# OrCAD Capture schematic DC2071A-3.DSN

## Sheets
1 PAGE1: size Custom; rev: 1
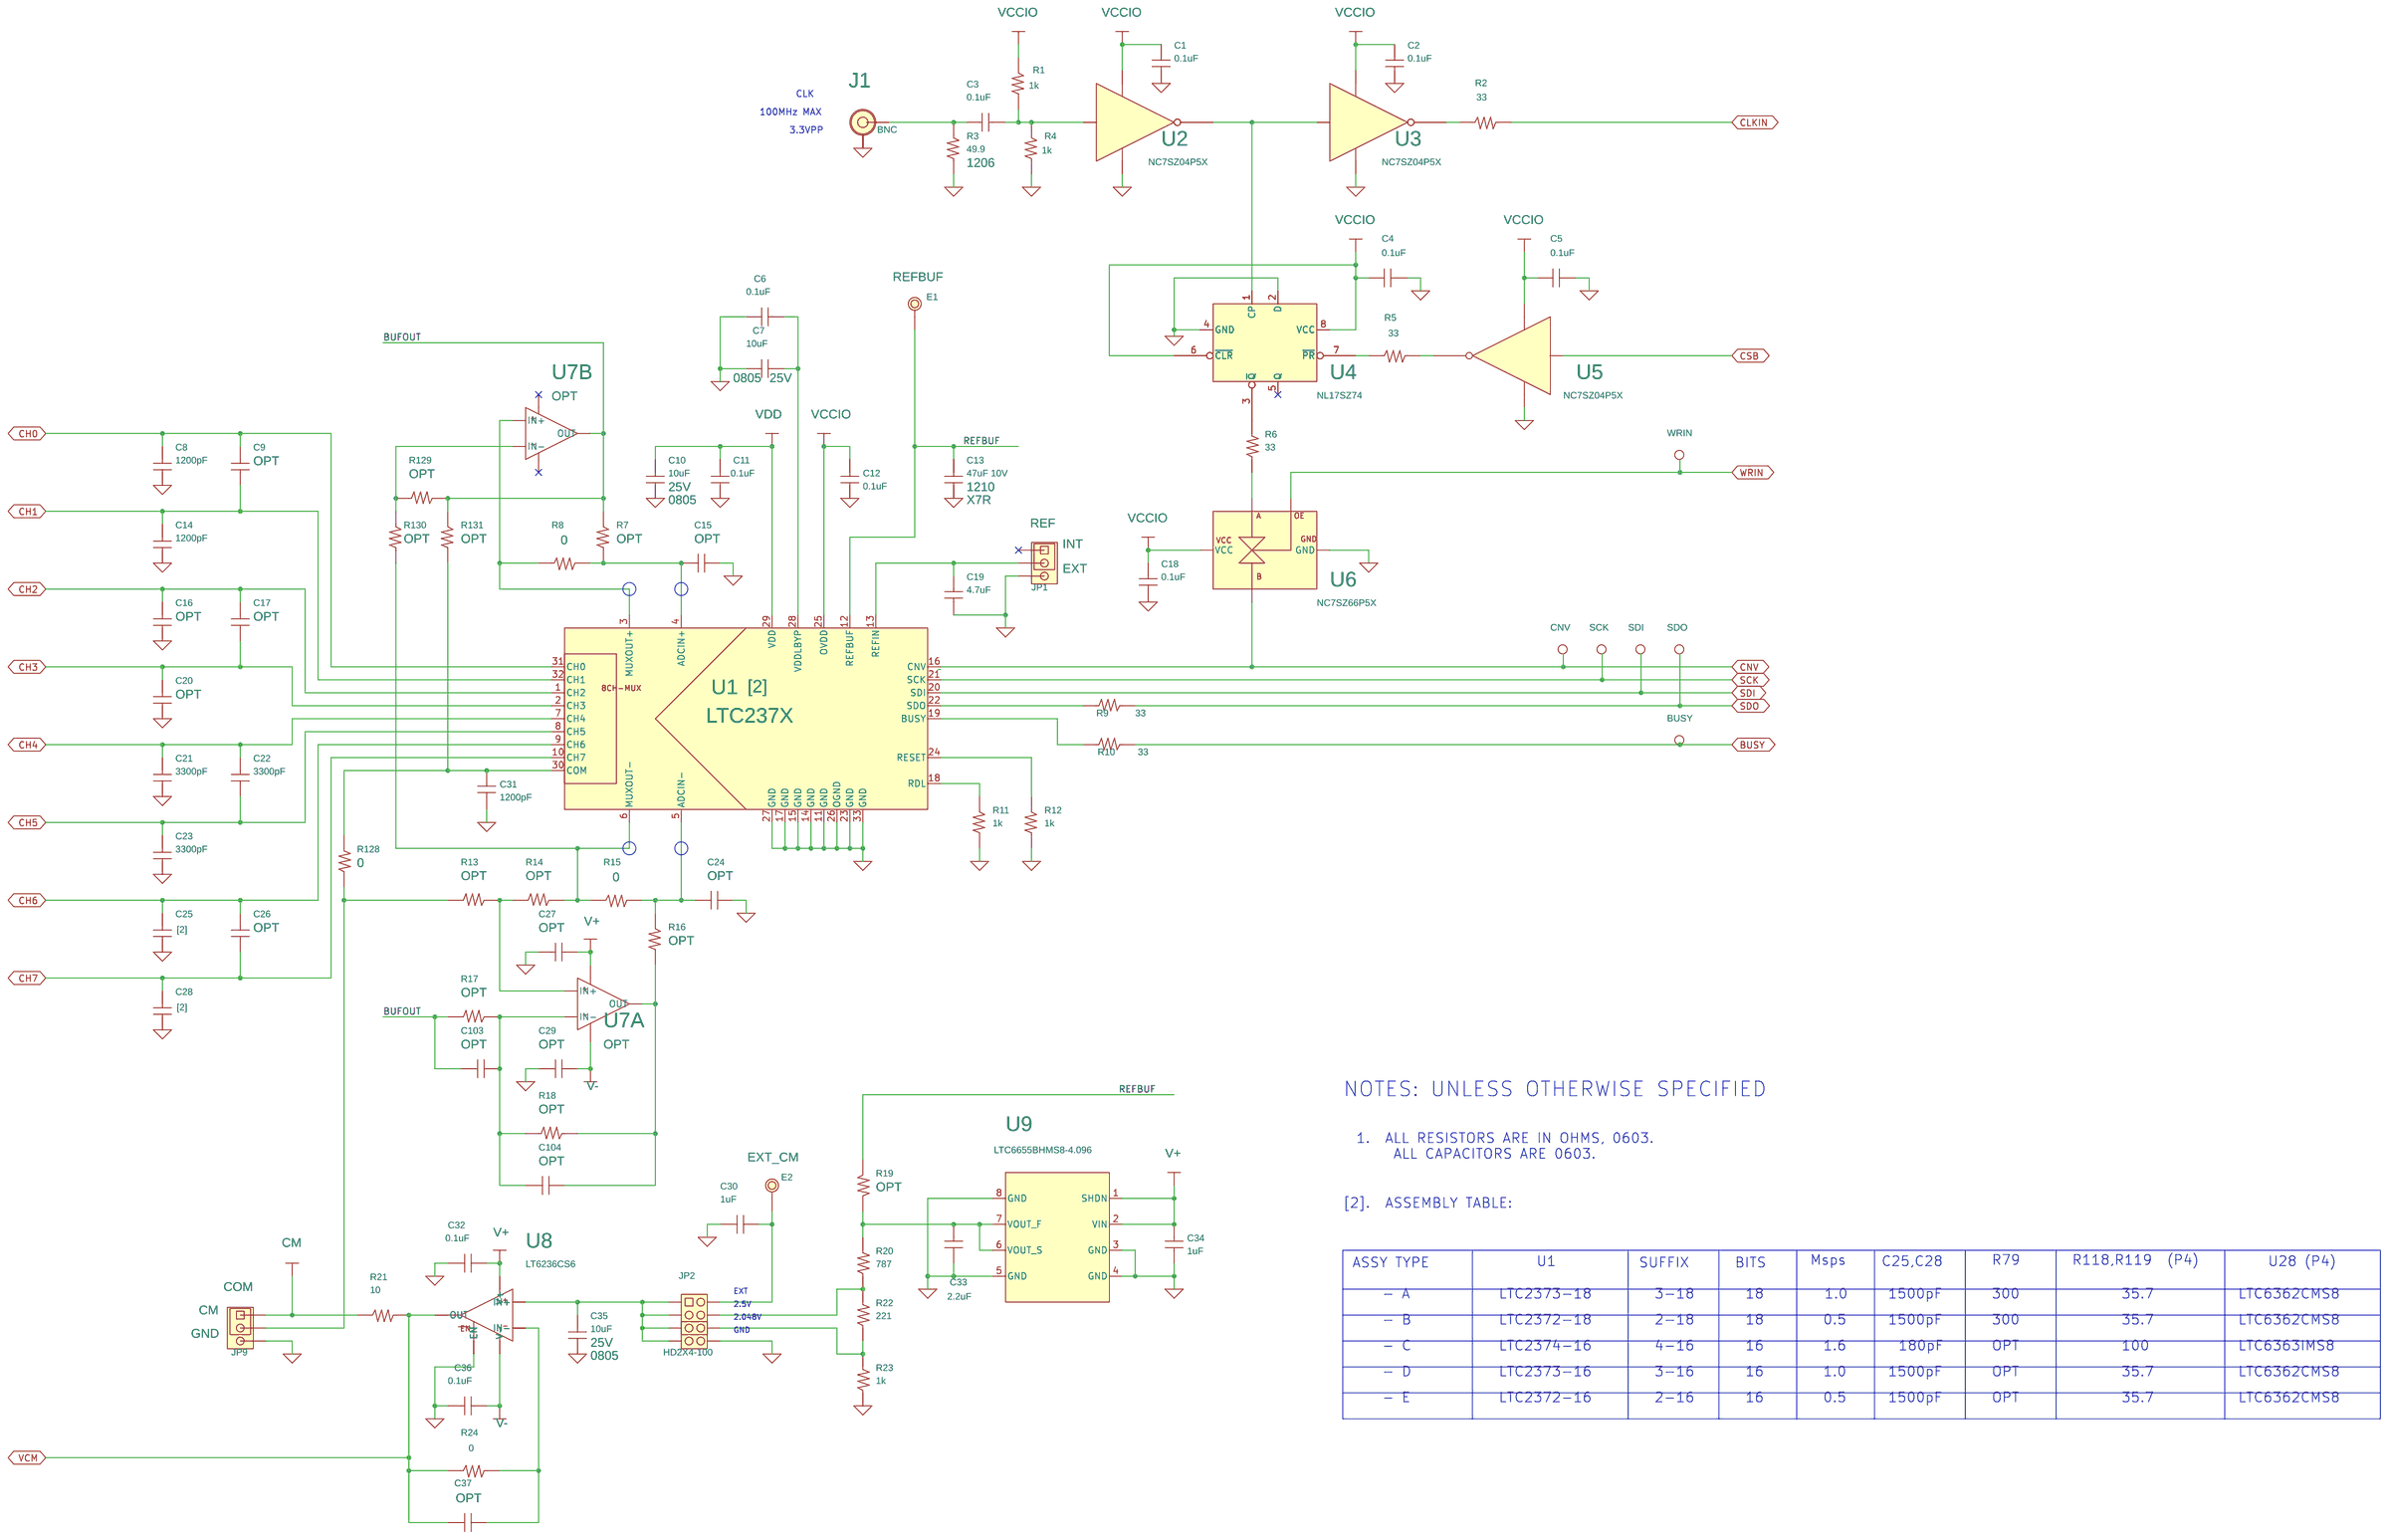
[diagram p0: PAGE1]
2 PAGE2: size B; title: 8-CHANNEL, HIGH SPEED, SERIAL, SAR, ADC; rev: 3; company: LTC237XCUH-18/16 FAMILY; note: DEMO CIRCUIT 2071A; note: B
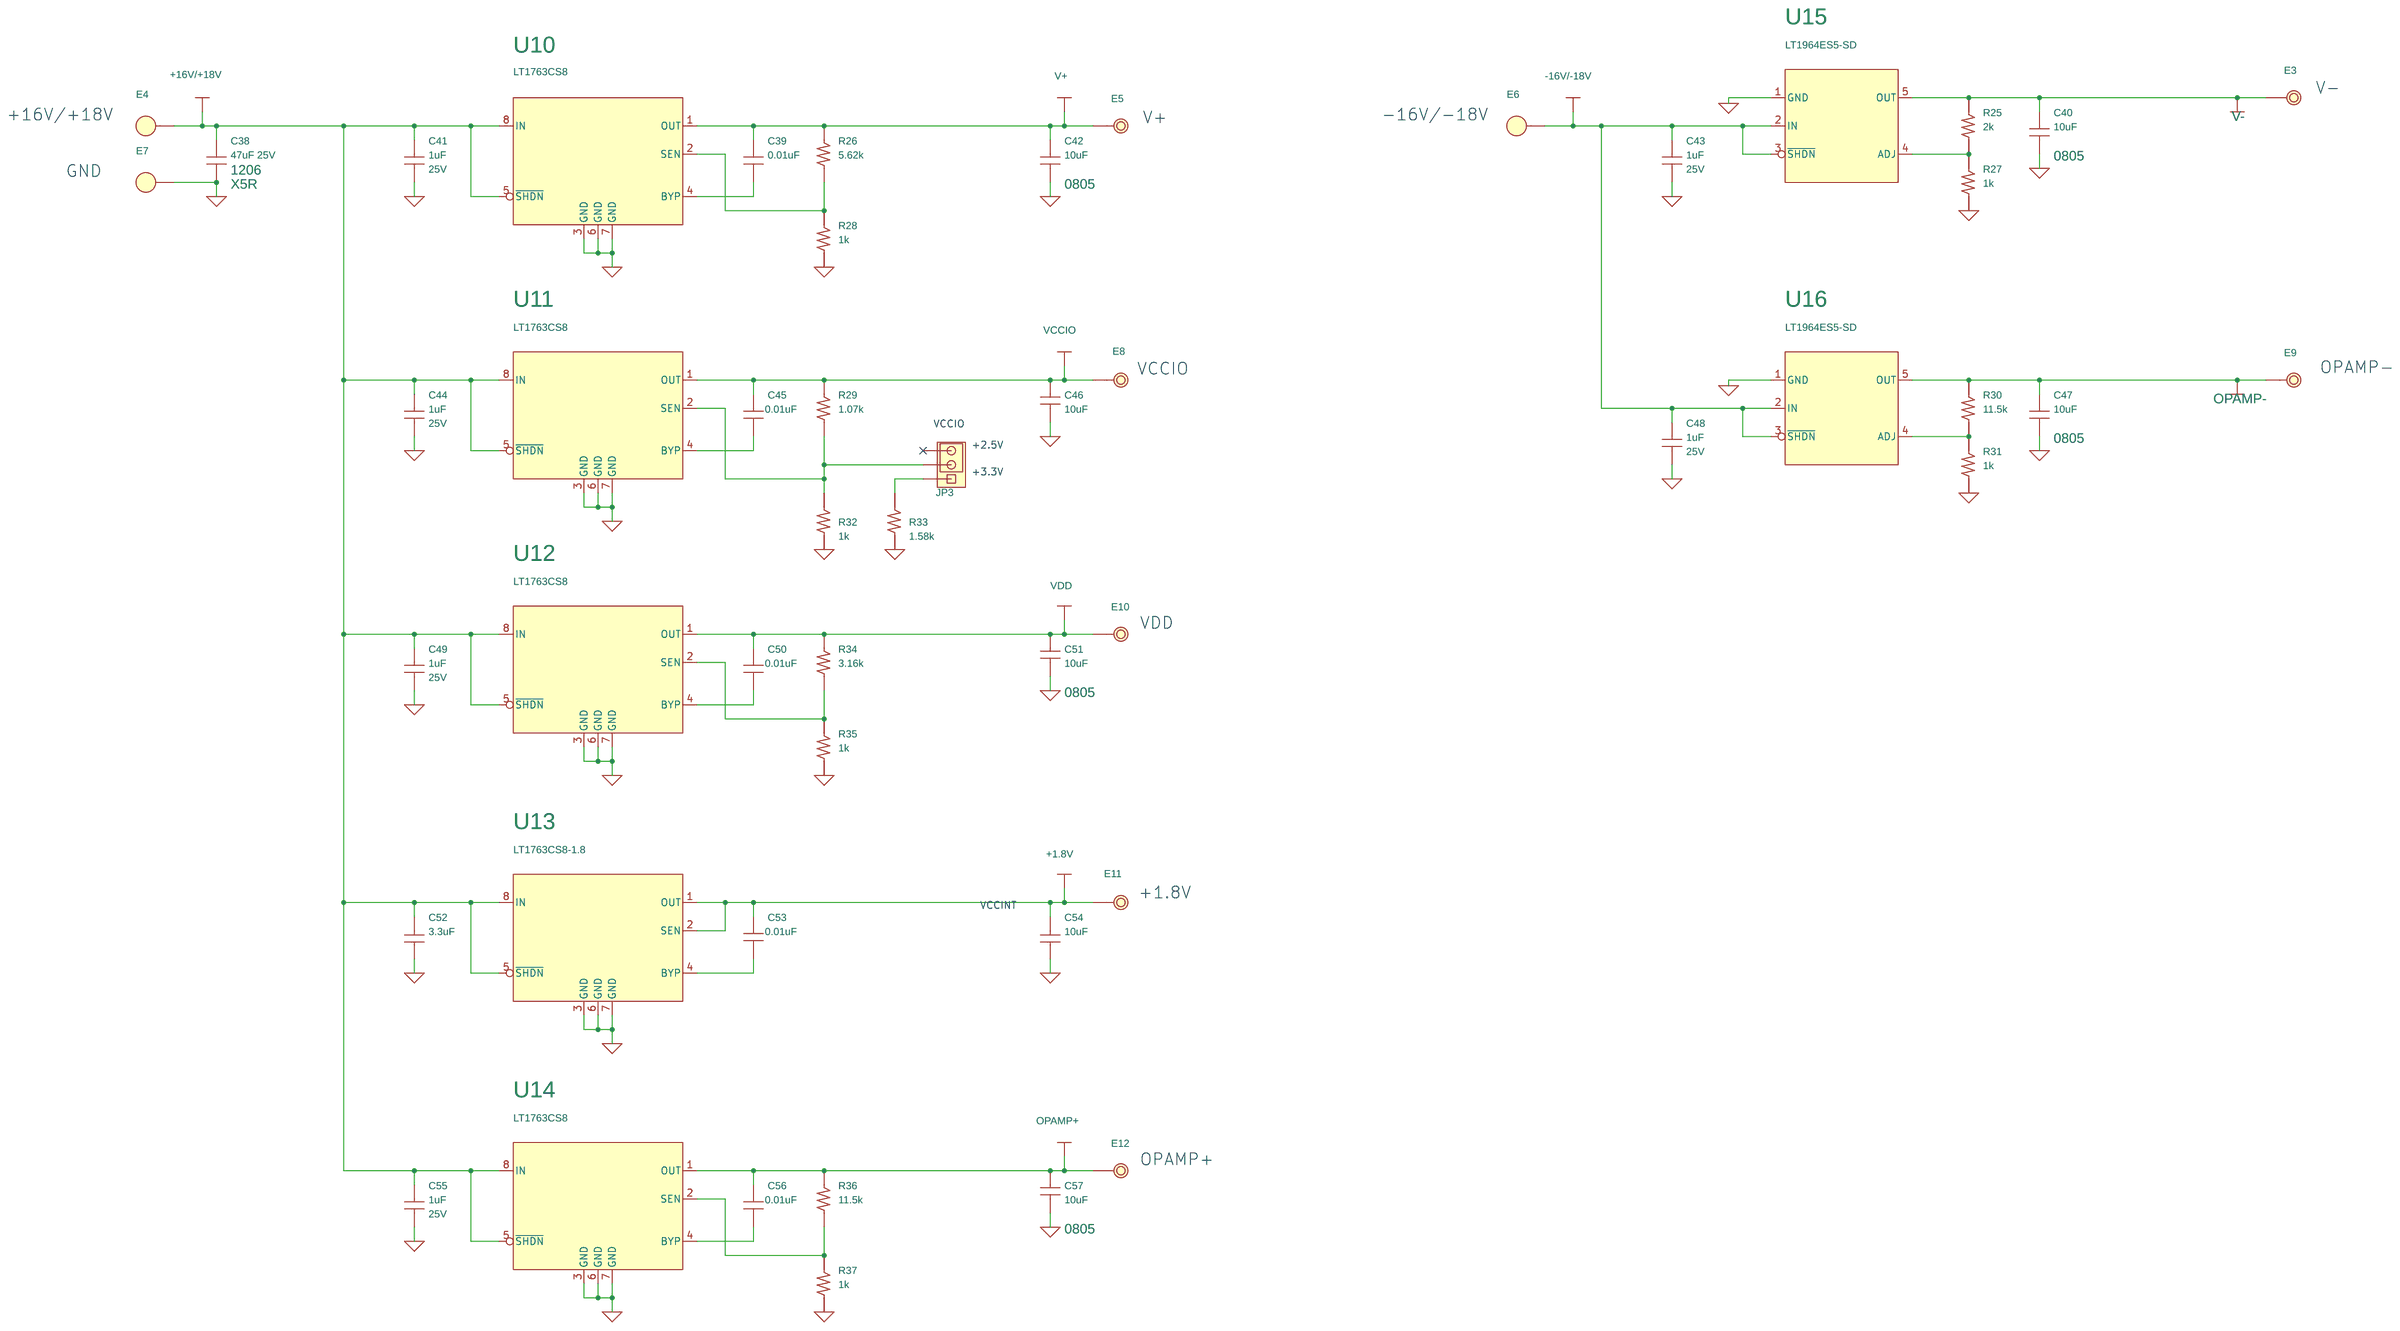
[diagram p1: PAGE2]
3 PAGE3: size B; title: 8-CHANNEL, HIGH SPEED, SERIAL, SAR, ADC; rev: 3; company: LTC237XCUH-18/16 FAMILY; note: DEMO CIRCUIT 2071A; note: B
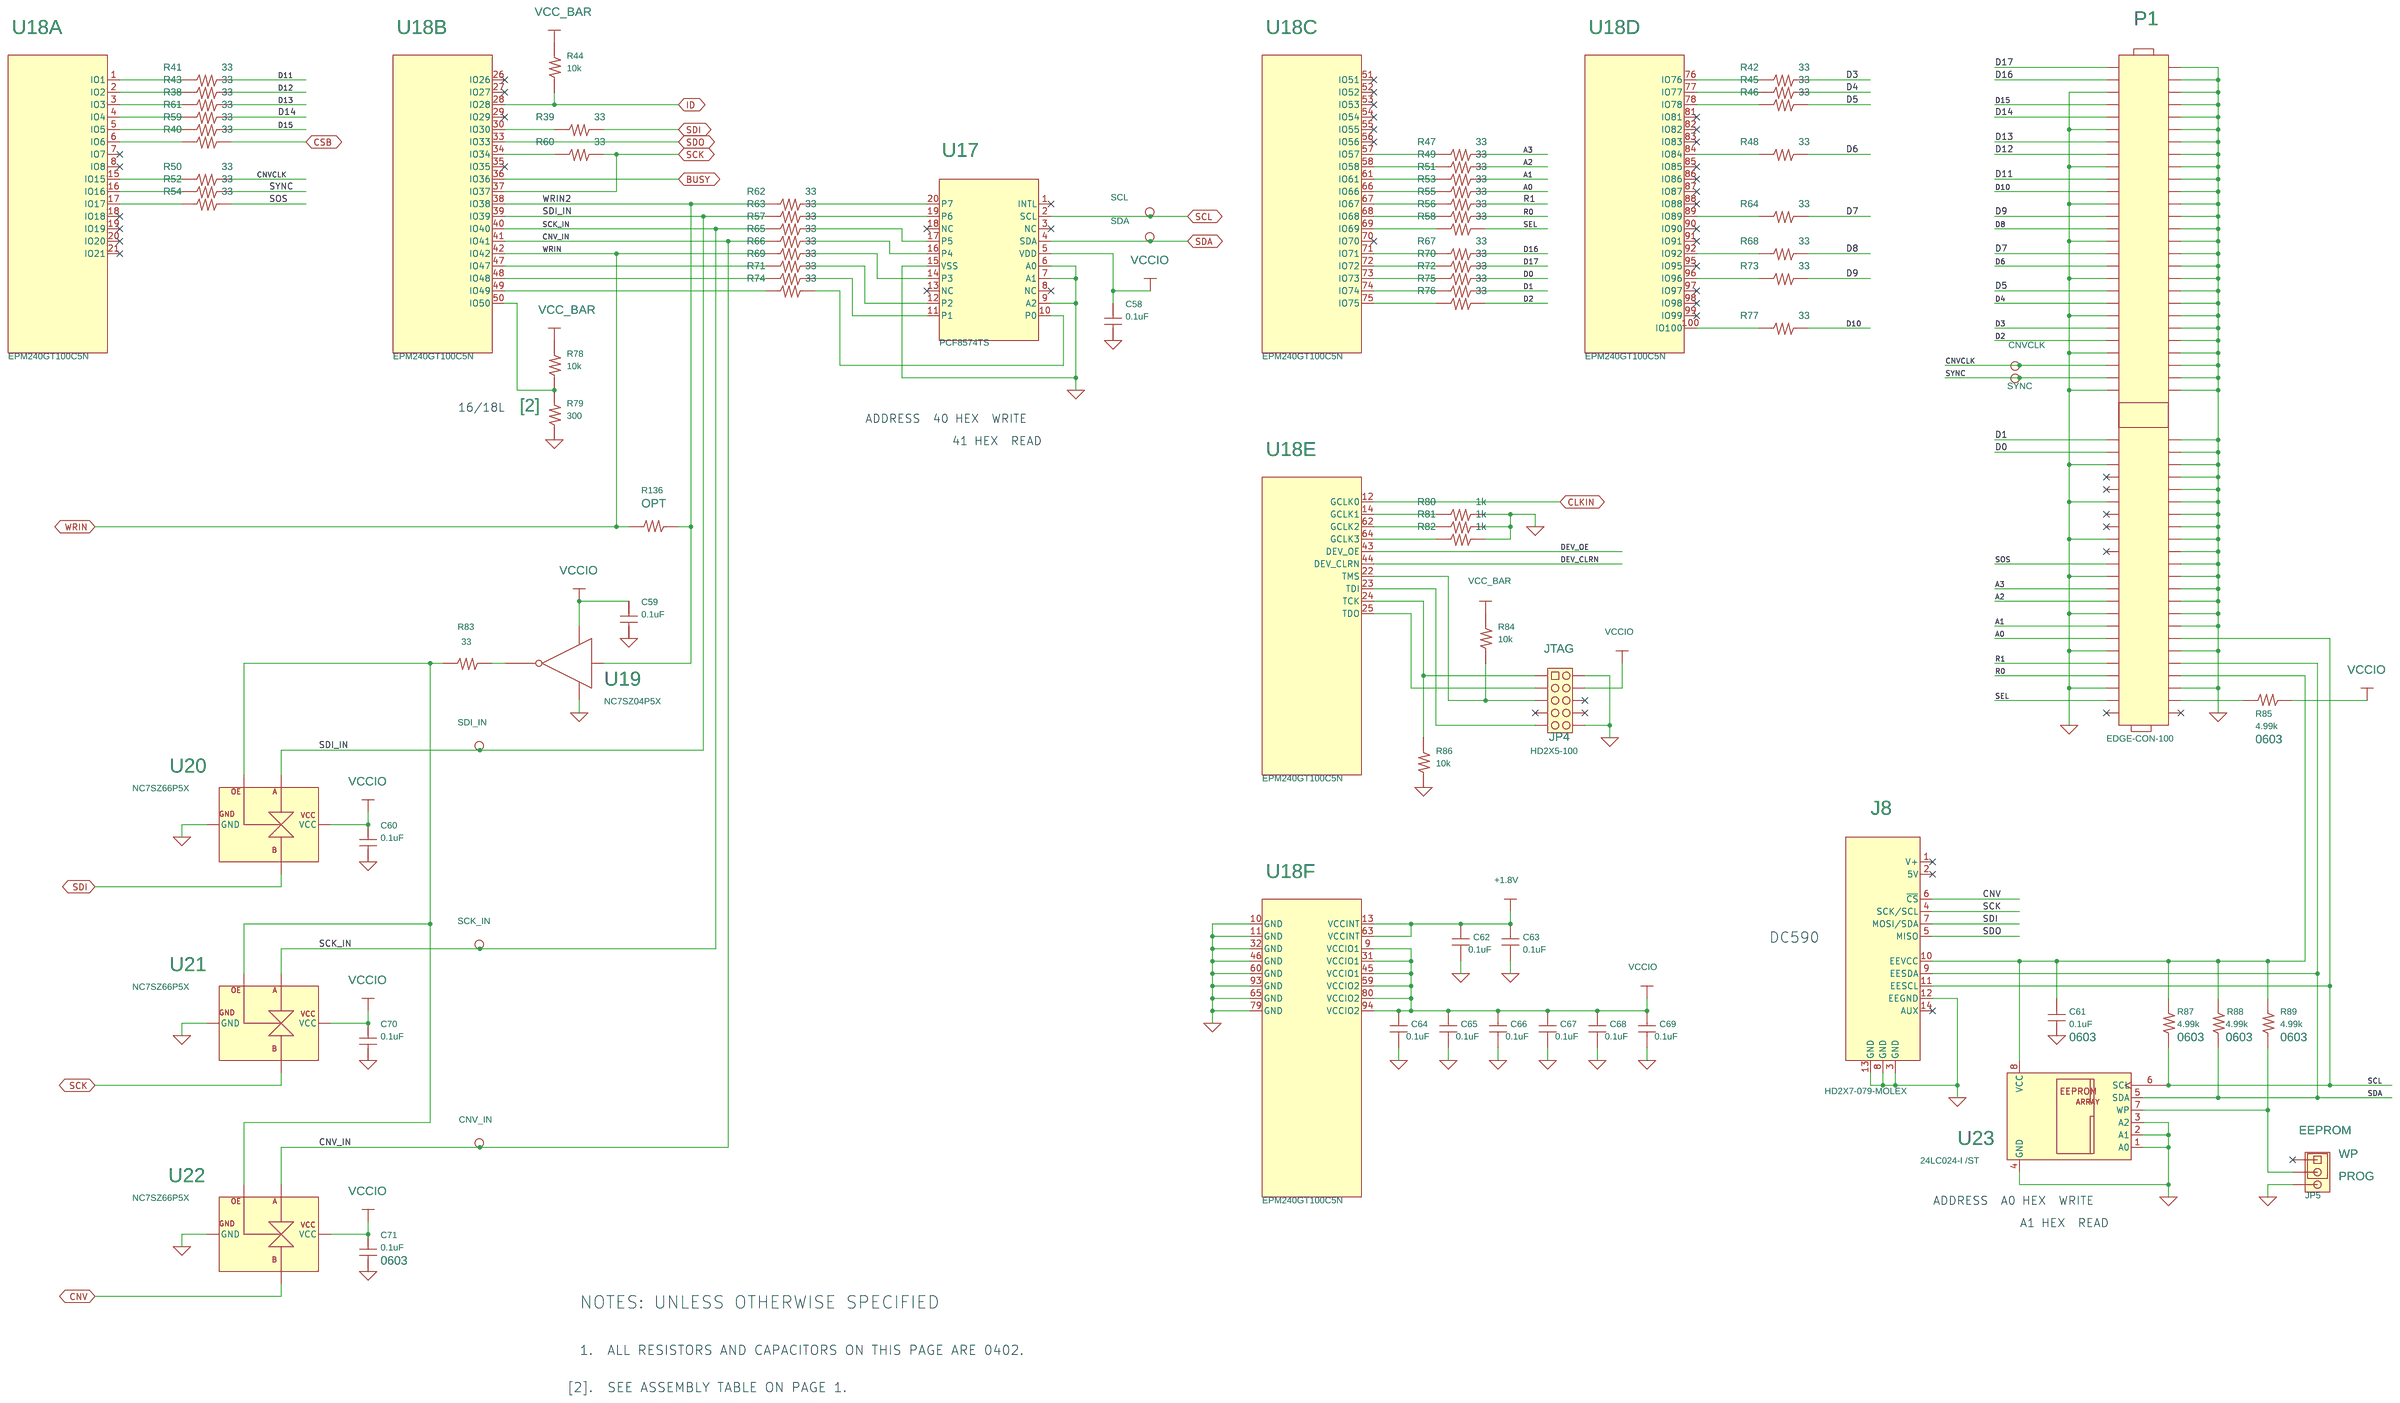
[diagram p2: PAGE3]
4 PAGE4: size B; title: 8-CHANNEL, HIGH SPEED, SERIAL, SAR, ADC; rev: 3; company: LTC237XCUH-18/16 FAMILY; note: DEMO CIRCUIT 2071A; note: B
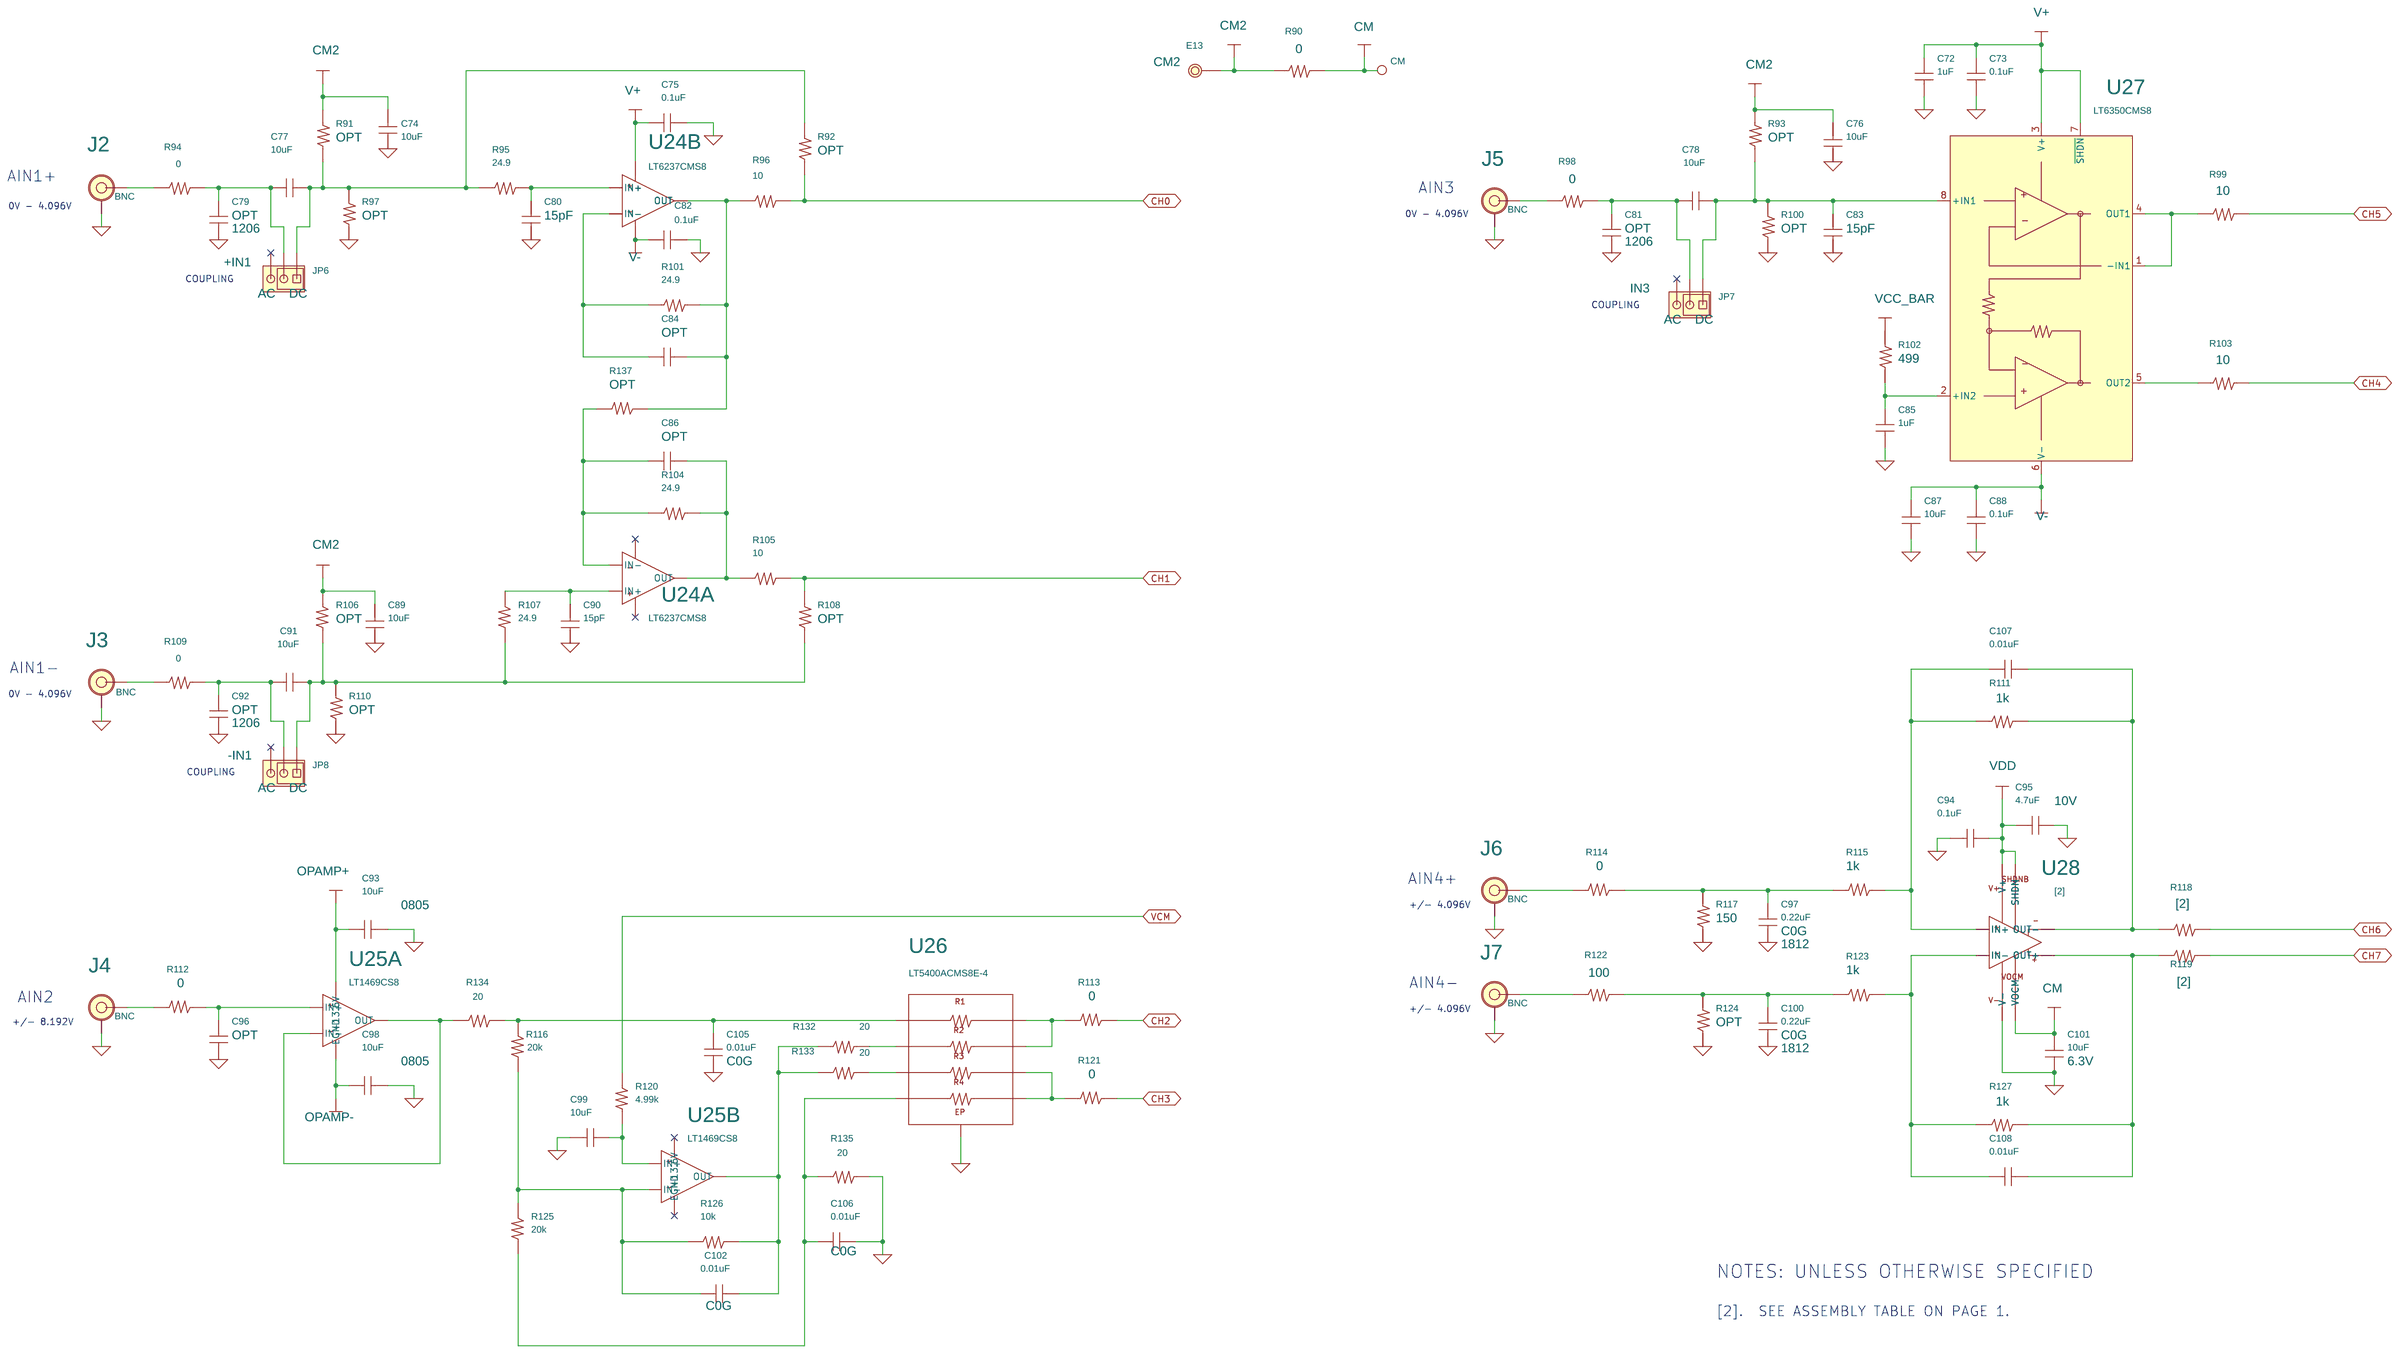
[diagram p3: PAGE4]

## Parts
sheet PAGE1
BUSY  E-060-035  [PAD060-035]
C1  0.1uF  [0603]
C2  0.1uF  [0603]
C3  0.1uF  [0603]
C4  0.1uF  [0603]
C5  0.1uF  [0603]
C6  0.1uF  [0603]
C7  10uF  [0805]
C8  1200pF  [0603]
C9  C-0603  [0603]
C10  10uF  [0805]
C11  0.1uF  [0603]
C12  0.1uF  [0603]
C13  47uF 10V  [1210]
C14  1200pF  [0603]
C15  C-0603  [0603]
C16  C-0603  [0603]
C17  C-0603  [0603]
C18  0.1uF  [0603]
C19  4.7uF  [0603]
C20  C-0603  [0603]
C21  3300pF  [0603]
C22  3300pF  [0603]
C23  3300pF  [0603]
C24  C-0603  [0603]
C25  [2]  [0603]
C26  C-0603  [0603]
C27  C-0603  [0603]
C28  [2]  [0603]
C29  C-0603  [0603]
C30  1uF  [0603]
C31  1200pF  [0603]
C32  0.1uF  [0603]
C33  2.2uF  [0603]
C34  1uF  [0603]
C35  10uF  [0805]
C36  0.1uF  [0603]
C37  C-0603  [0603]
C103  C-0603  [0603]
C104  C-0603  [0603]
CNV  E-060-035  [PAD060-035]
E1  MILL-MAX-2308  [MILL-MAX-2308]
E2  MILL-MAX-2308  [MILL-MAX-2308]
J1  BNC  [BNC5]
JP1  HD1X3-100  [HD1X3-100]
JP2  HD2X4-100  [HD2X4-100]
JP9  HD1X3-100  [HD1X3-100]
R1  1k  [0603]
R2  33  [0603]
R3  49.9  [1206]
R4  1k  [0603]
R5  33  [0603]
R6  33  [0603]
R7  R-0603  [0603]
R8  0  [0603]
R9  33  [0603]
R10  33  [0603]
R11  1k  [0603]
R12  1k  [0603]
R13  R-0603  [0603]
R14  R-0603  [0603]
R15  0  [0603]
R16  R-0603  [0603]
R17  R-0603  [0603]
R18  R-0603  [0603]
R19  R-0603  [0603]
R20  787  [0603]
R21  10  [0603]
R22  221  [0603]
R23  1k  [0603]
R24  0  [0603]
R128  0  [0603]
R129  R-0603  [0603]
R130  R-0603  [0603]
R131  R-0603  [0603]
SCK  E-060-035  [PAD060-035]
SDI  E-060-035  [PAD060-035]
SDO  E-060-035  [PAD060-035]
U1  LTC237X  [QFN32UH-5X5]
U2  NC7SZ04P5X  [SC70-5]
U3  NC7SZ04P5X  [SC70-5]
U4  NL17SZ74  [US8]
U5  NC7SZ04P5X  [SC70-5]
U6  NC7SZ66P5X  [SC70-5]
U7  OPT-LT6237CMS8  [MS8]  (sections A,B)
U8  LT6236CS6  [TSOT23-6]
U9  LTC6655BHMS8-4.096  [MSOP8]
WRIN  E-060-035  [PAD060-035]
sheet PAGE2
C38  47uF 25V  [1206]
C39  0.01uF  [0603]
C40  10uF  [0805]
C41  1uF  [0603]
C42  10uF  [0805]
C43  1uF  [0603]
C44  1uF  [0603]
C45  0.01uF  [0603]
C46  10uF  [0603]
C47  10uF  [0805]
C48  1uF  [0603]
C49  1uF  [0603]
C50  0.01uF  [0603]
C51  10uF  [0805]
C52  3.3uF  [0603]
C53  0.01uF  [0603]
C54  10uF  [0603]
C55  1uF  [0603]
C56  0.01uF  [0603]
C57  10uF  [0805]
E3  MILL-MAX-2308  [MILL-MAX-2308]
E4  MILL-MAX-2501  [MILL-MAX-2501]
E5  MILL-MAX-2308  [MILL-MAX-2308]
E6  MILL-MAX-2501  [MILL-MAX-2501]
E7  MILL-MAX-2501  [MILL-MAX-2501]
E8  MILL-MAX-2308  [MILL-MAX-2308]
E9  MILL-MAX-2308  [MILL-MAX-2308]
E10  MILL-MAX-2308  [MILL-MAX-2308]
E11  MILL-MAX-2308  [MILL-MAX-2308]
E12  MILL-MAX-2308  [MILL-MAX-2308]
JP3  HD1X3-100  [HD1X3-100]
R25  2k  [0603]
R26  5.62k  [0603]
R27  1k  [0603]
R28  1k  [0603]
R29  1.07k  [0603]
R30  11.5k  [0603]
R31  1k  [0603]
R32  1k  [0603]
R33  1.58k  [0603]
R34  3.16k  [0603]
R35  1k  [0603]
R36  11.5k  [0603]
R37  1k  [0603]
U10  LT1763CS8  [SO8]
U11  LT1763CS8  [SO8]
U12  LT1763CS8  [SO8]
U13  LT1763CS8-1.8  [SO8]
U14  LT1763CS8  [SO8]
U15  LT1964ES5-SD  [SOT23-S5]
U16  LT1964ES5-SD  [SOT23-S5]
sheet PAGE3
C58  0.1uF  [0402]
C59  0.1uF  [0402]
C60  0.1uF  [0402]
C61  0.1uF  [0603]
C62  0.1uF  [0402]
C63  0.1uF  [0402]
C64  0.1uF  [0402]
C65  0.1uF  [0402]
C66  0.1uF  [0402]
C67  0.1uF  [0402]
C68  0.1uF  [0402]
C69  0.1uF  [0402]
C70  0.1uF  [0402]
C71  0.1uF  [0603]
CNV_IN  E-060-035  [PAD060-035]
CNVCLK  E-060-035  [PAD060-035]
J8  HD2X7-079-MOLEX  [HD2X7-079-MOLEX]
JP4  HD2X5-100  [HD2X5-100]
JP5  HD1X3-100  [HD1X3-100]
P1  EDGE-CON-100  [CON-GOLD-100P-TB]
R38  33  [0402]
R39  33  [0402]
R40  33  [0402]
R41  33  [0402]
R42  33  [0402]
R43  33  [0402]
R44  10k  [0402]
R45  33  [0402]
R46  33  [0402]
R47  33  [0402]
R48  33  [0402]
R49  33  [0402]
R50  33  [0402]
R51  33  [0402]
R52  33  [0402]
R53  33  [0402]
R54  33  [0402]
R55  33  [0402]
R56  33  [0402]
R57  33  [0402]
R58  33  [0402]
R59  33  [0402]
R60  33  [0402]
R61  33  [0402]
R62  33  [0402]
R63  33  [0402]
R64  33  [0402]
R65  33  [0402]
R66  33  [0402]
R67  33  [0402]
R68  33  [0402]
R69  33  [0402]
R70  33  [0402]
R71  33  [0402]
R72  33  [0402]
R73  33  [0402]
R74  33  [0402]
R75  33  [0402]
R76  33  [0402]
R77  33  [0402]
R78  10k  [0402]
R79  300  [0402]
R80  1k  [0402]
R81  1k  [0402]
R82  1k  [0402]
R83  33  [0402]
R84  10k  [0402]
R85  4.99k  [0603]
R86  10k  [0402]
R87  4.99k  [0603]
R88  4.99k  [0603]
R89  4.99k  [0603]
R136  R-0402  [0402]
SCK_IN  E-060-035  [PAD060-035]
SCL  E-060-035  [PAD060-035]
SDA  E-060-035  [PAD060-035]
SDI_IN  E-060-035  [PAD060-035]
SYNC  E-060-035  [PAD060-035]
U17  PCF8574TS  [SSOP20]
U18  EPM240GT100C5N  [TQFP100]  (sections A,B,C,D,E,F)
U19  NC7SZ04P5X  [SC70-5]
U20  NC7SZ66P5X  [SC70-5]
U21  NC7SZ66P5X  [SC70-5]
U22  NC7SZ66P5X  [SC70-5]
U23  24LC024-I /ST  [TSSOP8]
sheet PAGE4
C72  1uF  [0603]
C73  0.1uF  [0603]
C74  10uF  [0603]
C75  0.1uF  [0603]
C76  10uF  [0603]
C77  10uF  [0603]
C78  10uF  [0603]
C79  C-1206  [1206]
C80  15pF  [0603]
C81  C-1206  [1206]
C82  0.1uF  [0603]
C83  15pF  [0603]
C84  C-0603  [0603]
C85  1uF  [0603]
C86  C-0603  [0603]
C87  10uF  [0603]
C88  0.1uF  [0603]
C89  10uF  [0603]
C90  15pF  [0603]
C91  10uF  [0603]
C92  C-1206  [1206]
C93  10uF  [0805]
C94  0.1uF  [0603]
C95  4.7uF  [0603]
C96  C-0603  [0603]
C97  0.22uF  [1812]
C98  10uF  [0805]
C99  10uF  [0603]
C100  0.22uF  [1812]
C101  10uF  [0603]
C102  0.01uF  [0603]
C105  0.01uF  [0603]
C106  0.01uF  [0603]
C107  0.01uF  [0603]
C108  0.01uF  [0603]
CM  E-060-035  [PAD060-035]
E13  MILL-MAX-2308  [MILL-MAX-2308]
J2  BNC  [BNC5]
J3  BNC  [BNC5]
J4  BNC  [BNC5]
J5  BNC  [BNC5]
J6  BNC  [BNC5]
J7  BNC  [BNC5]
JP6  HD1X3-100  [HD1X3-100]
JP7  HD1X3-100  [HD1X3-100]
JP8  HD1X3-100  [HD1X3-100]
R90  0  [0603]
R91  R-0603  [0603]
R92  R-0603  [0603]
R93  R-0603  [0603]
R94  0  [0603]
R95  24.9  [0603]
R96  10  [0603]
R97  R-0603  [0603]
R98  0  [0603]
R99  10  [0603]
R100  R-0603  [0603]
R101  24.9  [0603]
R102  499  [0603]
R103  10  [0603]
R104  24.9  [0603]
R105  10  [0603]
R106  R-0603  [0603]
R107  24.9  [0603]
R108  R-0603  [0603]
R109  0  [0603]
R110  R-0603  [0603]
R111  1k  [0603]
R112  0  [0603]
R113  0  [0603]
R114  0  [0603]
R115  1k  [0603]
R116  20k  [0603]
R117  150  [0603]
R118  [2]  [0603]
R119  [2]  [0603]
R120  4.99k  [0603]
R121  0  [0603]
R122  100  [0603]
R123  1k  [0603]
R124  R-0603  [0603]
R125  20k  [0603]
R126  10k  [0603]
R127  1k  [0603]
R132  20  [0603]
R133  20  [0603]
R134  20  [0603]
R135  20  [0603]
R137  R-0603  [0603]
U24  LT6237CMS8  [MS8]  (sections A,B)
U25  LT1469CS8  [SO8]  (sections A,B)
U26  LT5400ACMS8E-4  [MS8E]
U27  LT6350CMS8  [MS8]
U28  [2]  [MS8]

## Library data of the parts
BUSY CM CNV CNV_IN CNVCLK SCK SCK_IN SCL SDA SDI SDI_IN SDO SYNC WRIN = E-060-035
C1-C6 C8 C11 C12 C14 C18 C19 C21-C23 C25 C28 C30-C34 C36 C39 C42 C45 C46 C50-C54 C56-C78 C80 C82 C83 C85 C87-C91 C93 C94 C98 C99 C107 C108 = CAP-NP
C7 C10 C35 = CAP-NP: 1st Part Field: 25V
C9 C15-C17 C20 C24 C26 C27 C29 C37 C79 C81 C84 C86 C92 C96 C103 C104 = CAP-NP: OPT: OPT
C13 = CAP-NP: 1st Part Field: X7R
E1 = E-064: 1st Part Field: REFBUF
E2 = E-064: 1st Part Field: EXT_CM
J1-J7 = BNC
JP1 = HD1X3: 1st Part Field: REF; 2nd Part Field: EXT; 3rd Part Field: INT
JP2 = HD2X4-100_0
JP9 = HD1X3: 1st Part Field: COM; 2nd Part Field: GND; 3rd Part Field: CM
R1-R6 R8-R12 R15 R20-R78 R80-R90 R94-R96 R98 R99 R101-R105 R107 R109 R111-R123 R125-R128 R132-R135 = R
R7 R13 R14 R16-R19 R91-R93 R97 R100 R106 R108 R110 R124 R129-R131 R136 R137 = R: OPT: OPT
U1 = LTC237XCUH-QFN32UH-5X5: 1st Part Field: [2]
U2 U3 U5 = NC7SZ04P5X-ONE
U4 = NL17SZ74-US8
U6 U20-U22 = NC7SZ66P5X-SC70-5
U7 = LT6237CMS8-MS8: OPT: OPT
U8 = LT6236CS6-TSOT23-6
U9 = LTC6655AHMSH-5
C38 = CAP-NP: 1ST PART FIELD: 16V; 2nd Part Field: X5R; 5TH PART FIELD: 1210
C40 C41 C43 C44 C47-C49 C55 = CAP-NP: 1ST PART FIELD: 25V
E3 E5 E8-E12 = E-064
E4 E6 E7 = E-094
JP3 = HD1X3_0
U10-U14 = LT1763CS8-SO8
U15 U16 = LT1964ES5-SD-SOT23-5
J8 = HD2X7-079-MOLEX
JP4 = HD2X5-100_1: 1st Part Field: JTAG
JP5 = HD1X3: 1st Part Field: EEPROM; 2nd Part Field: PROG; 3rd Part Field: WP
P1 = CON-EDGE-100P-TB
R79 = R: 1st Part Field: [2]
U17 = PCF8574TS-SSOP20
U18 = EPM240-MAXII-TQFP100
U19 = NC7SZ04P5X-SC70-5
U23 = 24LC025-I_ST
C95 = CAP-NP: 1st Part Field: 10V
C97 C100 C102 C105 C106 = CAP-NP: 1st Part Field: C0G
C101 = CAP-NP: 1st Part Field: 6.3V
E13 = E-064: 1st Part Field: CM2
JP6 = HD1X3: 1st Part Field: +IN1; 2nd Part Field: AC; 3rd Part Field: DC
JP7 = HD1X3: 1st Part Field: IN3; 2nd Part Field: AC; 3rd Part Field: DC
JP8 = HD1X3: 1st Part Field: -IN1; 2nd Part Field: AC; 3rd Part Field: DC
U24 = LT1819CMS8-MS8
U25 = LT1469CS8
U26 = LT5400ACMS8E-4-MS8E
U27 = LT6350CMS8-MS8
U28 = LTC6362CMS8-MS8_0: 1ST PART FIELD: LTC6362CMS8

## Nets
+1.8V: C53.1 C54.2 C62.1 C63.1 E11.1(A) U13.1(OUT) U13.2(SEN) U18.13(VCCINT) U18.63(VCCINT)
+16V/+18V: C38.1 C41.1 C44.1 C49.1 C52.2 C55.1 E4.1(A) U10.5(~{SHDN}) U10.8(IN) U11.5(~{SHDN}) U11.8(IN) U12.5(~{SHDN}) U12.8(IN) U13.5(~{SHDN}) U13.8(IN) U14.5(~{SHDN}) U14.8(IN)
-16V/-18V: C43.1 C48.1 E6.1(A) U15.2(IN) U15.3(~{SHDN}) U16.2(IN) U16.3(~{SHDN})
GND: C1.2 C2.2 C4.2 C5.2 C6.1 C7.1 C8.1 C10.1 C11.1 C12.1 C13.1 C14.1 C15.1 C16.1 C18.2 C19.2 C20.1 C21.1 C23.1 C24.1 C25.1 C27.2 C28.1 C29.2 C30.2 C31.2 C32.2 C33.1 C34.1 C35.1 C36.2 C38.2 C40.2 C41.2 C42.2 C43.2 C44.2 C46.2 C47.2 C48.2 C49.2 C51.2 C52.1 C54.1 C55.2 C57.2 C58.2 C59.2 C60.2 C61.1 C62.2 C63.2 C64.2 C65.2 C66.2 C67.2 C68.2 C69.2 C70.2 C71.2 C72.2 C73.2 C74.1 C75.2 C76.1 C79.2 C80.2 C81.2 C82.2 C83.2 C85.2 C87.1 C88.1 C89.1 C90.1 C92.2 C93.2 C94.2 C95.1 C96.2 C97.2 C98.2 C99.2 C100.2 C101.1 C105.2 C106.2 E7.1(A) J1.2 J1.3 J1.4 J1.5 J2.2 J2.3 J2.4 J2.5 J3.2 J3.3 J3.4 J3.5 J4.2 J4.3 J4.4 J4.5 J5.2 J5.3 J5.4 J5.5 J6.2 J6.3 J6.4 J6.5 J7.2 J7.3 J7.4 J7.5 J8.3(GND) J8.8(GND) J8.12(EEGND) J8.13(GND) JP1.3 JP2.8 JP4.2 JP4.10 JP5.3 JP9.3 P1.1 P1.3 P1.5 P1.6 P1.7 P1.9 P1.11 P1.12 P1.13 P1.15 P1.17 P1.18 P1.19 P1.21 P1.23 P1.24 P1.25 P1.27 P1.29 P1.30 P1.31 P1.33 P1.35 P1.36 P1.37 P1.39 P1.41 P1.42 P1.43 P1.45 P1.47 P1.48 P1.49 P1.51 P1.53 P1.54 P1.55 P1.57 P1.59 P1.60 P1.61 P1.63 P1.65 P1.66 P1.67 P1.69 P1.71 P1.72 P1.73 P1.75 P1.77 P1.78 P1.79 P1.81 P1.83 P1.84 P1.85 P1.89 P1.90 P1.95 P1.96 R3.2 R4.2 R11.2 R12.2 R23.1 R27.2 R28.2 R31.2 R32.2 R33.2 R35.2 R37.2 R79.1 R80.2 R81.2 R82.2 R86.1 R97.1 R100.1 R110.1 R117.1 R124.1 R135.2 U1.11(GND) U1.14(GND) U1.15(GND) U1.17(GND) U1.23(GND) U1.26(OGND) U1.27(GND) U1.33(GND) U2.3 U3.3 U4.2(D) U4.4(GND) U5.3 U6.3(GND) U8.5(EN) U9.3(GND) U9.4(GND) U9.5(GND) U9.8(GND) U10.3(GND) U10.6(GND) U10.7(GND) U11.3(GND) U11.6(GND) U11.7(GND) U12.3(GND) U12.6(GND) U12.7(GND) U13.3(GND) U13.6(GND) U13.7(GND) U14.3(GND) U14.6(GND) U14.7(GND) U15.1(GND) U16.1(GND) U17.6(A0) U17.7(A1) U17.9(A2) U17.15(VSS) U18.10(GND) U18.11(GND) U18.32(GND) U18.46(GND) U18.60(GND) U18.65(GND) U18.79(GND) U18.93(GND) U19.3 U20.3(GND) U21.3(GND) U22.3(GND) U23.1(A0) U23.2(A1) U23.3(A2) U23.4(GND) U26.9 U28.6(V-)
VCCIO: C1.1 C2.1 C4.1 C5.1 C12.2 C18.1 C45.1 C46.1 C58.1 C59.1 C60.1 C64.1 C65.1 C66.1 C67.1 C68.1 C69.1 C70.1 C71.1 E8.1(A) JP4.4 R1.1 R29.1 R44.2 R78.2 R84.2 R85.1 U1.25(OVDD) U2.5 U3.5 U4.6(~{CLR}) U4.8(VCC) U5.5 U6.5(VCC) U11.1(OUT) U17.5(VDD) U18.9(VCCIO1) U18.31(VCCIO1) U18.45(VCCIO1) U18.59(VCCIO2) U18.80(VCCIO2) U18.94(VCCIO2) U19.5 U20.5(VCC) U21.5(VCC) U22.5(VCC)
VDD: C10.2 C11.2 C50.1 C51.1 C94.1 C95.2 E10.1(A) R34.1 U1.29(VDD) U12.1(OUT) U28.3(V+) U28.7(SHDN)
A0: P1.88 R53.2
A1: P1.86 R51.2
A2: P1.82 R49.2
A3: P1.80 R47.2
BUFOUT: C103.2 R7.1 R17.2 R129.1 R131.1 U7.7(OUT)
BUSY: BUSY.1 R10.1 U18.36(IO36)
CH0: C8.2 C9.2 R92.1 R96.2 U1.31(CH0)
CH1: C9.1 C14.2 R105.2 R108.2 U1.32(CH1)
CH2: C16.2 C17.2 R113.1 U1.1(CH2)
CH3: C17.1 C20.2 R121.1 U1.2(CH3)
CH4: C21.2 C22.2 R103.2 U1.7(CH4)
CH5: C22.1 C23.2 R99.2 U1.8(CH5)
CH6: C25.2 C26.2 R118.2 U1.9(CH6)
CH7: C26.1 C28.2 R119.2 U1.10(CH7)
CLKIN: R2.2 U18.12(GCLK0)
CM: C101.2 CM.1 JP9.1 R21.1 R90.2 R102.2 U28.2(VOCM)
CM2: C74.2 C76.2 C89.2 E13.1(A) R90.1 R91.2 R93.2 R106.1
CNV: CNV.1 J8.6(~{CS}) U1.16(CNV) U6.2 U22.2
CNV_IN: CNV_IN.1 R65.1 U18.41(IO41) U22.1
CNVCLK: CNVCLK.1 P1.50 R50.2
CSB: R40.2 U5.2
D0: P1.58 R72.2
D1: P1.56 R75.2
D2: P1.46 R76.2
D3: P1.44 R42.2
D4: P1.40 R45.2
D5: P1.38 R46.2
D6: P1.34 R48.2
D7: P1.32 R64.2
D8: P1.28 R68.2
D9: P1.26 R73.2
D10: P1.22 R77.2
D11: P1.20 R41.2
D12: P1.16 R43.2
D13: P1.14 R38.2
D14: P1.10 R61.2
D15: P1.8 R59.2
D16: P1.4 R67.2
D17: P1.2 R70.2
DEV_CLRN: U18.44(DEV_CLRN)
DEV_OE: U18.43(DEV_OE)
ID: R44.1 U18.28(IO28)
OPAMP+: C56.1 C57.1 C93.1 E12.1(A) R36.1 U14.1(OUT) U25.8(+13.6V)
OPAMP-: C47.1 C98.1 E9.1(A) R30.1 U16.5(OUT) U25.4(EGND)
R0: P1.94 R56.2
R1: P1.92 R55.2
REFBUF: C13.2 E1.1(A) R19.1 U1.12(REFBUF)
SCK: J8.4(SCK/SCL) R60.2 SCK.1 U1.21(SCK) U18.37(IO37) U21.2
SCK_IN: R57.1 SCK_IN.1 U18.40(IO40) U21.1
SCL: J8.11(EESCL) P1.87 R87.1 SCL.1 U17.2(SCL) U23.6(SCL)
SDA: J8.9(EESDA) P1.91 R88.1 SDA.1 U17.4(SDA) U23.5(SDA)
SDI: J8.7(MOSI/SDA) R39.2 SDI.1 U1.20(SDI) U20.2
SDI_IN: R63.1 SDI_IN.1 U18.39(IO39) U20.1
SDO: J8.5(MISO) R9.1 SDO.1 U18.33(IO33)
SEL: P1.98 R58.2
SOS: P1.76 R54.2
SYNC: P1.52 R52.2 SYNC.1
V+: C27.1 C32.1 C34.2 C39.1 C42.1 C72.1 C73.1 C75.1 E5.1(A) R26.1 U7.8 U8.6(V+) U9.1(SHDN) U9.2(VIN) U10.1(OUT) U24.8 U27.3(V+) U27.7(~{SHDN})
V-: C29.1 C36.1 C40.1 C82.1 C87.2 C88.2 E3.1(A) R25.1 U7.4 U8.2(V-) U15.5(OUT) U24.4 U27.6(V-)
VCM: C37.2 R21.2 R24.1 R120.1 U8.1(OUT)
WRIN: R66.1 R136.2 U6.4 U18.42(IO42) WRIN.1
WRIN2: R62.1 R136.1 U18.38(IO38) U19.2
N928027: C3.2 R1.2 R4.1 U2.2
N928109: C3.1 J1.1 R3.1
N928437: U2.4 U3.2 U4.1(CP)
N929285: R5.1 U4.7(~{PR})
N938745: R25.2 R27.1 U15.4(ADJ)
N940093: C45.2 U11.4(BYP)
N940147: JP3.2 R29.2 R32.1 U11.2(SEN)
N979025: R2.1 U3.4
N1083481: R5.2 U5.4
N3254306: C61.2 J8.10(EEVCC) P1.93 R87.2 R88.2 R89.2 U23.8(VCC)
N3257370: JP5.2 R89.1 U23.7(WP)
N3261285: P1.97 R85.2
N4126329: R26.2 R28.1 U10.2(SEN)
N4126471: C39.2 U10.4(BYP)
N4139373: JP3.1 R33.1
N4148550: C50.2 U12.4(BYP)
N4148570: R34.2 R35.1 U12.2(SEN)
N4561890: C33.2 R19.2 R20.2 U9.6(VOUT_S) U9.7(VOUT_F)
N4562088: C37.1 R24.2 U8.4(IN-)
N4562124: C30.1 E2.1(A) JP2.2
N5914479: C35.2 JP2.1 JP2.3 JP2.5 JP2.7 U8.3(IN+)
N5929508: JP2.6 R22.1 R23.2
N5934257: JP2.4 R20.1 R22.2
N5983413: R9.2 U1.22(SDO)
N5983846: R10.2 U1.19(BUSY)
N5992639: R11.1 U1.18(RDL)
N5993083: R12.1 U1.24(RESET)
N6009573: C15.2 R7.2 R8.2 U1.4(ADCIN+)
N6020742: R8.1 U1.3(MUXOUT+) U7.5(IN+)
N6042083: C104.1 R16.2 R18.1 U7.1(OUT)
N6047568: R14.1 R15.1 R130.2 U1.6(MUXOUT-)
N6052885: C24.2 R15.2 R16.1 U1.5(ADCIN-)
N6059505: R13.1 R14.2 U7.3(IN+)
N6059990: C31.1 R128.2 R131.2 U1.30(COM)
N6060477: JP9.2 R13.2 R128.1
N6088227: R6.1 U6.1
N6126687: C19.1 JP1.2 U1.13(REFIN)
N6134194: R129.2 R130.1 U7.6(IN-)
N6147326: C103.1 C104.2 R17.1 R18.2 U7.2(IN-)
N6209595: C6.2 C7.2 U1.28(VDDLBYP)
N6741333: R83.1 U20.4 U21.4 U22.4
N6747679: R83.2 U19.4
N6762152: R41.1 U18.1(IO1)
N6766104: R38.1 U18.3(IO3)
N6766665: R61.1 U18.4(IO4)
N6767229: R59.1 U18.5(IO5)
N6767796: R40.1 U18.6(IO6)
N6774880: R43.1 U18.2(IO2)
N6780670: R50.1 U18.15(IO15)
N6780674: R52.1 U18.16(IO16)
N6780678: R54.1 U18.17(IO17)
N6831626: R39.1 U18.30(IO30)
N6832108: R60.1 U18.34(IO34)
N6843766: R78.1 R79.2 U18.50(IO50)
N6898596: R74.2 U17.10(P0)
N6927599: R69.1 U18.47(IO47)
N6929087: R62.2 U17.20(P7)
N6929569: R63.2 U17.19(P6)
N6930053: R57.2 U17.17(P5)
N6931029: R65.2 U17.16(P4)
N6932014: R66.2 U17.14(P3)
N6933006: R69.2 U17.12(P2)
N6934007: R71.2 U17.11(P1)
N6936560: R71.1 U18.48(IO48)
N6940616: R74.1 U18.49(IO49)
N6949796: R49.1 U18.58(IO58)
N6949800: R47.1 U18.57(IO57)
N6949852: R51.1 U18.61(IO61)
N6949888: R53.1 U18.66(IO66)
N6949892: R55.1 U18.67(IO67)
N6954615: R58.1 U18.69(IO69)
N6954619: R56.1 U18.68(IO68)
N6959902: R72.1 U18.73(IO73)
N6959906: R75.1 U18.74(IO74)
N6959954: R67.1 U18.71(IO71)
N6959958: R70.1 U18.72(IO72)
N6960547: R76.1 U18.75(IO75)
N6967615: R45.1 U18.77(IO77)
N6967619: R42.1 U18.76(IO76)
N6967671: R46.1 U18.78(IO78)
N6973246: R48.1 U18.84(IO84)
N6973850: R64.1 U18.89(IO89)
N6974457: R68.1 U18.92(IO92)
N6975067: R73.1 U18.96(IO96)
N6975680: R77.1 U18.100(IO100)
N7012178: R80.1 U18.14(GCLK1)
N7014741: R81.1 U18.62(GCLK2)
N7015577: R82.1 U18.64(GCLK3)
N7032552: JP4.5 R84.1 U18.22(TMS)
N7033746: JP4.9 U18.23(TDI)
N7034948: JP4.1 R86.2 U18.24(TCK)
N7036158: JP4.3 U18.25(TDO)
N7163771: C77.1 C79.1 JP6.2 R94.2
N7163885: C86.1 R104.1 R137.2 U24.2(IN-)
N7163969: C91.1 C92.1 JP8.2 R109.2
N7164029: J3.1 R109.1
N7164077: C84.2 R96.1 R101.2 R137.1 U24.7(OUT)
N7164207: C77.2 JP6.1 R91.1 R92.2 R95.1 R97.2
N7164215: C86.2 R104.2 R105.1 U24.1(OUT)
N7164309: C91.2 JP8.1 R106.2 R107.2 R108.1 R110.2
N7164409: C80.1 R95.2 U24.5(IN+)
N7164433: C90.2 R107.1 U24.3(IN+)
N7164481: C84.1 R101.1 U24.6(IN-)
N7164949: J2.1 R94.1
N7222758: C96.1 R112.1 U25.3(IN+)
N7222936: J4.1 R112.2
N7429418: C78.1 C81.1 JP7.2 R98.2
N7429450: C78.2 C83.1 JP7.1 R93.1 R100.2 U27.8(+IN1)
N7429546: J5.1 R98.1
N7436322: R99.1 U27.1(-IN1) U27.4(OUT1)
N7438874: R103.1 U27.5(OUT2)
N7467259: C85.1 R102.1 U27.2(+IN2)
N7497006: C100.1 R122.2 R123.1 R124.2
N7497112: J7.1 R122.1
N7605217: C108.1 R123.2 R127.1 U28.1(IN-)
N7610400: C108.2 R119.1 R127.2 U28.4(OUT+)
N7635091: C107.2 R111.2 R118.1 U28.5(OUT-)
N7644438: C107.1 R111.1 R115.1 U28.8(IN+)
N9298080: C53.2 U13.4(BYP)
N9658261: R30.2 R31.1 U16.4(ADJ)
N9666408: R36.2 R37.1 U14.2(SEN)
N9666538: C56.2 U14.4(BYP)
N9773682: C97.1 R114.1 R115.2 R117.2
N9790236: R134.1 U25.1(OUT) U25.2(IN-)
N9802748: C102.1 R116.2 R125.1 R126.1 U25.6(IN-)
N9813292: C99.1 R120.2 U25.5(IN+)
N9829453: C105.1 R116.1 R134.2 U26.1
N9829911: R132.2 U26.2
N9830371: C102.2 R126.2 R132.1 R133.1 U25.7(OUT)
N9830373: R133.2 U26.3
N9832706: C106.1 R125.2 R135.1 U26.4
N9833882: R113.2 U26.7 U26.8
N9834822: R121.2 U26.5 U26.6
N10060312: J6.1 R114.2
N10709215: R6.2 U4.3(~{Q})

Not connected (* = marked no-connect by the designer): J8 1(V+)* 2(5V)* 14(AUX)*; JP1 1*; JP3 3*; JP4 6* 7* 8*; JP5 1*; JP6 3*; JP7 3*; JP8 3*; P1 62* 64* 68* 70* 74* 99* 100*; U4 5(Q)*; U17 1(INTL)* 3(NC)* 8(NC)* 13(NC)* 18(NC)*; U18 7(IO7)* 8(IO8)* 18(IO18)* 19(IO19)* 20(IO20)* 21(IO21)* 26(IO26)* 27(IO27)* 29(IO29)* 35(IO35)* 51(IO51)* 52(IO52)* 53(IO53)* 54(IO54)* 55(IO55)* 56(IO56)* 70(IO70)* 81(IO81)* 82(IO82)* 83(IO83)* 85(IO85)* 86(IO86)* 87(IO87)* 88(IO88)* 90(IO90)* 91(IO91)* 95(IO95)* 97(IO97)* 98(IO98)* 99(IO99)*

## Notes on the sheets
sheet 1
- CLK
- 100MHz MAX
- 3.3VPP
- NOTES: UNLESS OTHERWISE SPECIFIED
- 1.  ALL RESISTORS ARE IN OHMS, 0603.
       ALL CAPACITORS ARE 0603.
- [2].  ASSEMBLY TABLE:
- ASSY TYPE
- U1
- SUFFIX
- BITS
- Msps
- C25,C28
- R79
- R118,R119  (P4)
- U28 (P4)
- EXT
- - A
- LTC2373-18
- 3-18
- 18
- 1.0
- 1500pF
- 300
- 35.7
- LTC6362CMS8
- 2.5V
- 2.048V
- GND
- - B
- LTC2372-18
- 2-18
- 18
- 0.5
- 1500pF
- 300
- 35.7
- LTC6362CMS8
- - C
- LTC2374-16
- 4-16
- 16
- 1.6
- 180pF
- OPT
- 100
- LTC6363IMS8
- - D
- LTC2373-16
- 3-16
- 16
- 1.0
- 1500pF
- OPT
- 35.7
- LTC6362CMS8
- - E
- LTC2372-16
- 2-16
- 16
- 0.5
- 1500pF
- OPT
- 35.7
- LTC6362CMS8
sheet 2
- V-
- +16V/+18V
- V+
- -16V/-18V
- GND
- VCCIO
- OPAMP-
- VCCIO
- +2.5V
- +3.3V
- VDD
- +1.8V
- VCCINT
- OPAMP+
sheet 3
- 16/18L
- ADDRESS  40 HEX  WRITE
- 41 HEX  READ
- DC590
- ADDRESS  A0 HEX  WRITE
- A1 HEX  READ
- NOTES: UNLESS OTHERWISE SPECIFIED
- 1.  ALL RESISTORS AND CAPACITORS ON THIS PAGE ARE 0402.
- [2].  SEE ASSEMBLY TABLE ON PAGE 1.
sheet 4
- AIN1+
- AIN3
- 0V - 4.096V
- 0V - 4.096V
- COUPLING
- COUPLING
- AIN1-
- 0V - 4.096V
- COUPLING
- AIN4+
- +/- 4.096V
- AIN4-
- AIN2
- +/- 4.096V
- +/- 8.192V
- NOTES: UNLESS OTHERWISE SPECIFIED
- [2].  SEE ASSEMBLY TABLE ON PAGE 1.
